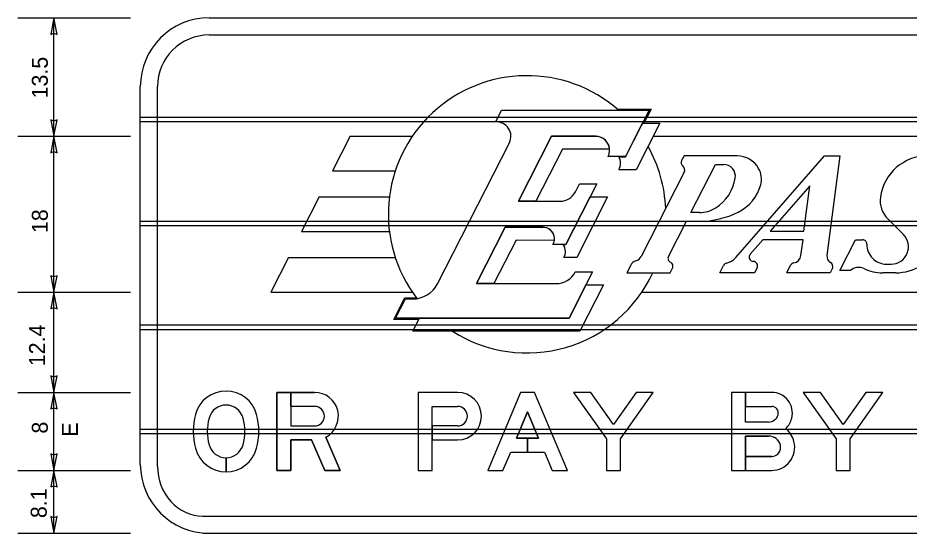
# Model space of a CAD drawing. Extents: x 319706 to 320346, y 1621790 to 1622121.
# Drawn here: x 319878.9 to 319957, y 1621942.3 to 1621987.5 of the extents above; entities that cross this region are included whole.
import ezdxf

# ---------------------------------------------------------------- set-up
doc = ezdxf.new("R2010")
doc.units = 0
for name, color, linetype in [('1', 7, 'Continuous'), ('52', 7, 'Continuous'), ('GSBWFill', 7, 'Continuous'), ('GSColorFill', 7, 'Continuous'), ('GSOutline', 7, 'Continuous'), ('SignPanel', 7, 'Continuous')]:
    doc.layers.add(name, color=color, linetype=linetype)

msp = doc.modelspace()

# ---------------------------------------------------------------- linework, layer by layer
at = {"layer": '1'}
for p, q in [((319878.894, 1621987.477), (319888.758, 1621987.477)), ((319882.055, 1621977.088), (319882.055, 1621987.477)), ((319878.894, 1621977.088), (319888.758, 1621977.088)), ((319882.055, 1621963.418), (319882.055, 1621977.088)), ((319878.894, 1621963.418), (319888.758, 1621963.418)), ((319882.055, 1621954.644), (319882.055, 1621963.418)), ((319878.894, 1621954.644), (319888.758, 1621954.644)), ((319882.055, 1621947.803), (319882.055, 1621954.644)), ((319878.894, 1621947.803), (319888.758, 1621947.803)), ((319882.055, 1621942.302), (319882.055, 1621947.803)), ((319878.894, 1621942.302), (319888.758, 1621942.302))]:
    msp.add_line(p, q, dxfattribs=at)
at = {"layer": '52'}
for p, q in [((319882.055, 1621987.477), (319881.775, 1621986.027)), ((319882.325, 1621986.027), (319882.055, 1621987.477)), ((319881.775, 1621986.027), (319882.055, 1621986.137)), ((319882.055, 1621986.137), (319882.325, 1621986.027)), ((319882.055, 1621978.428), (319881.785, 1621978.538)), ((319881.785, 1621978.538), (319882.055, 1621977.088)), ((319882.055, 1621977.088), (319882.335, 1621978.538)), ((319882.335, 1621978.538), (319882.055, 1621978.428)), ((319882.055, 1621977.088), (319881.775, 1621975.638)), ((319882.325, 1621975.638), (319882.055, 1621977.088)), ((319881.775, 1621975.638), (319882.055, 1621975.748)), ((319882.055, 1621975.748), (319882.325, 1621975.638)), ((319882.055, 1621964.758), (319881.785, 1621964.868)), ((319881.785, 1621964.868), (319882.055, 1621963.418)), ((319882.055, 1621963.418), (319882.335, 1621964.868)), ((319882.335, 1621964.868), (319882.055, 1621964.758)), ((319882.055, 1621963.418), (319881.775, 1621961.968)), ((319882.325, 1621961.968), (319882.055, 1621963.418)), ((319881.775, 1621961.968), (319882.055, 1621962.078)), ((319882.055, 1621962.078), (319882.325, 1621961.968)), ((319882.055, 1621955.984), (319881.785, 1621956.094)), ((319881.785, 1621956.094), (319882.055, 1621954.644)), ((319882.055, 1621954.644), (319882.335, 1621956.094)), ((319882.335, 1621956.094), (319882.055, 1621955.984)), ((319882.055, 1621954.644), (319881.775, 1621953.194)), ((319882.325, 1621953.194), (319882.055, 1621954.644)), ((319881.775, 1621953.194), (319882.055, 1621953.304)), ((319882.055, 1621953.304), (319882.325, 1621953.194)), ((319882.055, 1621949.143), (319881.785, 1621949.253)), ((319881.785, 1621949.253), (319882.055, 1621947.803)), ((319882.055, 1621947.803), (319882.335, 1621949.253)), ((319882.335, 1621949.253), (319882.055, 1621949.143)), ((319882.055, 1621947.803), (319881.775, 1621946.353)), ((319882.325, 1621946.353), (319882.055, 1621947.803)), ((319881.775, 1621946.353), (319882.055, 1621946.463)), ((319882.055, 1621946.463), (319882.325, 1621946.353)), ((319882.055, 1621943.642), (319881.785, 1621943.752)), ((319881.785, 1621943.752), (319882.055, 1621942.302)), ((319882.055, 1621942.302), (319882.335, 1621943.752)), ((319882.335, 1621943.752), (319882.055, 1621943.642))]:
    msp.add_line(p, q, dxfattribs=at)
at = {"layer": 'GSBWFill'}
for p, q in [((319915.192, 1621953.413), (319917.416, 1621953.413)), ((319897.13, 1621948.915), (319897.13, 1621947.683)), ((319897.131, 1621947.683), (319897.131, 1621948.915))]:
    msp.add_line(p, q, dxfattribs=at)
for points in [[(319905.859, 1621950.713), (319907.119, 1621947.803), (319905.777, 1621947.803), (319904.622, 1621950.471), (319902.809, 1621950.471), (319902.809, 1621947.803), (319901.577, 1621947.803), (319901.577, 1621954.644), (319902.809, 1621954.644), (319902.809, 1621951.703), (319904.885, 1621951.703)], [(319902.809, 1621953.413), (319902.809, 1621954.644), (319904.885, 1621954.644)], [(319917.416, 1621954.644), (319913.961, 1621954.644), (319913.961, 1621947.803), (319915.192, 1621947.803), (319915.192, 1621953.413)], [(319944.654, 1621952.045), (319942.627, 1621952.045), (319942.627, 1621954.644), (319941.395, 1621954.644), (319941.395, 1621947.803), (319942.627, 1621947.803)], [(319944.919, 1621954.644), (319942.627, 1621954.644), (319942.627, 1621953.413), (319944.919, 1621953.413)], [(319904.885, 1621953.413), (319902.809, 1621953.413)], [(319917.416, 1621951.703), (319915.193, 1621951.703), (319915.193, 1621950.471), (319917.416, 1621950.471)], [(319942.627, 1621947.803), (319942.627, 1621950.813), (319944.654, 1621950.813)], [(319944.919, 1621949.034), (319942.627, 1621949.034), (319942.627, 1621947.803), (319944.919, 1621947.803)]]:
    msp.add_lwpolyline(points, dxfattribs=at)
for points in [[(319924.5, 1621950.642), (319923.539, 1621950.642), (319923.539, 1621949.411), (319925.017, 1621949.411), (319925.692, 1621947.803), (319927.028, 1621947.803), (319924.155, 1621954.644), (319922.923, 1621954.644), (319920.05, 1621947.803), (319921.385, 1621947.803), (319922.061, 1621949.411), (319923.539, 1621949.411), (319923.539, 1621950.642), (319922.578, 1621950.642), (319923.539, 1621952.93)], [(319931.68, 1621950.574), (319934.554, 1621954.644), (319933.046, 1621954.644), (319931.065, 1621951.837), (319929.083, 1621954.644), (319927.575, 1621954.644), (319930.449, 1621950.574), (319930.449, 1621947.803), (319931.68, 1621947.803)], [(319951.795, 1621950.574), (319954.668, 1621954.644), (319953.161, 1621954.644), (319951.179, 1621951.837), (319949.197, 1621954.644), (319947.69, 1621954.644), (319950.563, 1621950.574), (319950.563, 1621947.803), (319951.795, 1621947.803)]]:
    msp.add_lwpolyline(points, close=True, dxfattribs=at)
for centre, radius, start, end in [((319897.13, 1621951.991), 2.773, 14.96177, 165.03823), ((319904.885, 1621952.558), 2.087, 297.837, 90), ((319944.919, 1621952.831), 1.813, 345.52249, 90), ((319897.13, 1621951.991), 1.541, 14.96177, 165.03823), ((319904.885, 1621952.558), 0.855, 270, 90), ((319944.919, 1621952.831), 0.582, 345.52249, 90), ((319900.004, 1621951.224), 5.747, 165.03823, 194.96177), ((319900.004, 1621951.224), 4.515, 165.03823, 194.96177), ((319894.257, 1621951.224), 4.515, 345.03823, 14.96177), ((319894.257, 1621951.224), 5.747, 345.03823, 14.96177), ((319944.654, 1621952.9), 0.855, 270, 345.52249), ((319944.654, 1621952.9), 2.087, 316.7114, 345.52249), ((319944.654, 1621949.753), 2.292, 14.47751, 48.4921), ((319944.654, 1621949.753), 1.06, 14.47751, 90), ((319897.13, 1621950.456), 2.773, 194.96177, 270), ((319897.13, 1621950.456), 1.541, 194.96177, 270), ((319897.13, 1621950.456), 1.541, 270.01272, 345.03823), ((319897.13, 1621950.456), 2.773, 270.00707, 345.03823), ((319944.919, 1621949.821), 2.018, 270, 14.47751), ((319944.919, 1621949.821), 0.787, 270, 14.47751)]:
    msp.add_arc(centre, radius, start, end, dxfattribs=at)
for major_axis in [(0, 2.087), (0, 0.855)]:
    msp.add_ellipse((319917.416, 1621952.558), major_axis=major_axis, ratio=0.999994, start_param=3.141593, end_param=6.283185, dxfattribs=at)
at = {"layer": 'GSColorFill'}
for p, q in [((319915.192, 1621953.413), (319917.416, 1621953.413)), ((319897.13, 1621948.915), (319897.13, 1621947.683)), ((319897.131, 1621947.683), (319897.131, 1621948.915))]:
    msp.add_line(p, q, dxfattribs=at)
for points in [[(319905.859, 1621950.713), (319907.119, 1621947.803), (319905.777, 1621947.803), (319904.622, 1621950.471), (319902.809, 1621950.471), (319902.809, 1621947.803), (319901.577, 1621947.803), (319901.577, 1621954.644), (319902.809, 1621954.644), (319902.809, 1621951.703), (319904.885, 1621951.703)], [(319902.809, 1621953.413), (319902.809, 1621954.644), (319904.885, 1621954.644)], [(319917.416, 1621954.644), (319913.961, 1621954.644), (319913.961, 1621947.803), (319915.192, 1621947.803), (319915.192, 1621953.413)], [(319944.654, 1621952.045), (319942.627, 1621952.045), (319942.627, 1621954.644), (319941.395, 1621954.644), (319941.395, 1621947.803), (319942.627, 1621947.803)], [(319944.919, 1621954.644), (319942.627, 1621954.644), (319942.627, 1621953.413), (319944.919, 1621953.413)], [(319904.885, 1621953.413), (319902.809, 1621953.413)], [(319917.416, 1621951.703), (319915.193, 1621951.703), (319915.193, 1621950.471), (319917.416, 1621950.471)], [(319942.627, 1621947.803), (319942.627, 1621950.813), (319944.654, 1621950.813)], [(319944.919, 1621949.034), (319942.627, 1621949.034), (319942.627, 1621947.803), (319944.919, 1621947.803)]]:
    msp.add_lwpolyline(points, dxfattribs=at)
for points in [[(319924.5, 1621950.642), (319923.539, 1621950.642), (319923.539, 1621949.411), (319925.017, 1621949.411), (319925.692, 1621947.803), (319927.028, 1621947.803), (319924.155, 1621954.644), (319922.923, 1621954.644), (319920.05, 1621947.803), (319921.385, 1621947.803), (319922.061, 1621949.411), (319923.539, 1621949.411), (319923.539, 1621950.642), (319922.578, 1621950.642), (319923.539, 1621952.93)], [(319931.68, 1621950.574), (319934.554, 1621954.644), (319933.046, 1621954.644), (319931.065, 1621951.837), (319929.083, 1621954.644), (319927.575, 1621954.644), (319930.449, 1621950.574), (319930.449, 1621947.803), (319931.68, 1621947.803)], [(319951.795, 1621950.574), (319954.668, 1621954.644), (319953.161, 1621954.644), (319951.179, 1621951.837), (319949.197, 1621954.644), (319947.69, 1621954.644), (319950.563, 1621950.574), (319950.563, 1621947.803), (319951.795, 1621947.803)]]:
    msp.add_lwpolyline(points, close=True, dxfattribs=at)
for centre, radius, start, end in [((319897.13, 1621951.991), 2.773, 14.96177, 165.03823), ((319904.885, 1621952.558), 2.087, 297.837, 90), ((319944.919, 1621952.831), 1.813, 345.52249, 90), ((319897.13, 1621951.991), 1.541, 14.96177, 165.03823), ((319904.885, 1621952.558), 0.855, 270, 90), ((319944.919, 1621952.831), 0.582, 345.52249, 90), ((319900.004, 1621951.224), 5.747, 165.03823, 194.96177), ((319900.004, 1621951.224), 4.515, 165.03823, 194.96177), ((319894.257, 1621951.224), 4.515, 345.03823, 14.96177), ((319894.257, 1621951.224), 5.747, 345.03823, 14.96177), ((319944.654, 1621952.9), 0.855, 270, 345.52249), ((319944.654, 1621952.9), 2.087, 316.7114, 345.52249), ((319944.654, 1621949.753), 2.292, 14.47751, 48.4921), ((319944.654, 1621949.753), 1.06, 14.47751, 90), ((319897.13, 1621950.456), 2.773, 194.96177, 270), ((319897.13, 1621950.456), 1.541, 194.96177, 270), ((319897.13, 1621950.456), 1.541, 270.01272, 345.03823), ((319897.13, 1621950.456), 2.773, 270.00707, 345.03823), ((319944.919, 1621949.821), 2.018, 270, 14.47751), ((319944.919, 1621949.821), 0.787, 270, 14.47751)]:
    msp.add_arc(centre, radius, start, end, dxfattribs=at)
for major_axis in [(0, 2.087), (0, 0.855)]:
    msp.add_ellipse((319917.416, 1621952.558), major_axis=major_axis, ratio=0.999994, start_param=3.141593, end_param=6.283185, dxfattribs=at)
at = {"layer": 'GSOutline'}
for p, q in [((319915.192, 1621953.413), (319917.416, 1621953.413)), ((319915.192, 1621950.471), (319917.416, 1621950.471)), ((319941.395, 1621947.803), (319944.919, 1621947.803))]:
    msp.add_line(p, q, dxfattribs=at)
for points in [[(319904.885, 1621954.644), (319901.577, 1621954.644), (319901.577, 1621947.803), (319902.809, 1621947.803), (319902.809, 1621950.471), (319904.622, 1621950.471), (319905.777, 1621947.803), (319907.119, 1621947.803), (319905.859, 1621950.713)], [(319917.416, 1621954.644), (319913.961, 1621954.644), (319913.961, 1621947.803), (319915.192, 1621947.803), (319915.192, 1621950.471)], [(319944.919, 1621954.644), (319941.395, 1621954.644), (319941.395, 1621947.803)], [(319904.885, 1621953.413), (319902.809, 1621953.413), (319902.809, 1621951.703), (319904.885, 1621951.703)], [(319917.416, 1621951.703), (319915.192, 1621951.703), (319915.192, 1621953.413)], [(319944.654, 1621952.045), (319942.627, 1621952.045), (319942.627, 1621953.413), (319944.919, 1621953.413)], [(319944.654, 1621950.813), (319942.627, 1621950.813), (319942.627, 1621949.034), (319944.919, 1621949.034)]]:
    msp.add_lwpolyline(points, dxfattribs=at)
for points in [[(319922.061, 1621949.411), (319925.017, 1621949.411), (319925.692, 1621947.803), (319927.028, 1621947.803), (319924.155, 1621954.644), (319922.923, 1621954.644), (319920.05, 1621947.803), (319921.385, 1621947.803)], [(319931.68, 1621950.574), (319934.554, 1621954.644), (319933.046, 1621954.644), (319931.065, 1621951.837), (319929.083, 1621954.644), (319927.575, 1621954.644), (319930.449, 1621950.574), (319930.449, 1621947.803), (319931.68, 1621947.803)], [(319951.795, 1621950.574), (319954.668, 1621954.644), (319953.161, 1621954.644), (319951.179, 1621951.837), (319949.197, 1621954.644), (319947.69, 1621954.644), (319950.563, 1621950.574), (319950.563, 1621947.803), (319951.795, 1621947.803)], [(319924.5, 1621950.642), (319923.539, 1621952.93), (319922.578, 1621950.642)]]:
    msp.add_lwpolyline(points, close=True, dxfattribs=at)
for centre, radius, start, end in [((319897.13, 1621951.991), 2.773, 14.96177, 165.03823), ((319904.885, 1621952.558), 2.087, 297.837, 90), ((319944.919, 1621952.831), 1.813, 345.52249, 90), ((319897.13, 1621951.991), 1.541, 14.96177, 165.03823), ((319904.885, 1621952.558), 0.855, 270, 90), ((319944.919, 1621952.831), 0.582, 345.52249, 90), ((319900.004, 1621951.224), 5.747, 165.03823, 194.96177), ((319900.004, 1621951.224), 4.515, 165.03823, 194.96177), ((319894.257, 1621951.224), 4.515, 345.03823, 14.96177), ((319894.257, 1621951.224), 5.747, 345.03823, 14.96177), ((319944.654, 1621952.9), 0.855, 270, 345.52249), ((319944.654, 1621952.9), 2.087, 316.7114, 345.52249), ((319944.654, 1621949.753), 2.292, 14.47751, 48.4921), ((319944.654, 1621949.753), 1.06, 14.47751, 90), ((319897.13, 1621950.456), 2.773, 194.96177, 345.03823), ((319897.13, 1621950.456), 1.541, 194.96177, 345.03823), ((319944.919, 1621949.821), 2.018, 270, 14.47751), ((319944.919, 1621949.821), 0.787, 270, 14.47751)]:
    msp.add_arc(centre, radius, start, end, dxfattribs=at)
for major_axis in [(0, 2.087), (0, 0.855)]:
    msp.add_ellipse((319917.416, 1621952.558), major_axis=major_axis, ratio=0.999994, start_param=3.141593, end_param=6.283185, dxfattribs=at)
at = {"layer": 'SignPanel'}
for p, q in [((319895.646, 1621987.477), (319992.019, 1621987.477)), ((319895.646, 1621985.972), (319992.019, 1621985.972)), ((319889.623, 1621948.326), (319889.623, 1621981.453)), ((319891.129, 1621948.167), (319891.129, 1621981.453)), ((319931.402, 1621979.48), (319934.362, 1621979.48)), ((319934.362, 1621979.48), (319933.725, 1621978.228)), ((319889.623, 1621978.771), (319998.043, 1621978.771)), ((319920.749, 1621978.347), (319921.266, 1621979.367)), ((319921.266, 1621979.367), (319934.178, 1621979.367)), ((319934.178, 1621979.367), (319932.11, 1621975.306)), ((319889.623, 1621978.394), (319998.043, 1621978.394)), ((319932.106, 1621975.302), (319933.597, 1621978.228)), ((319932.106, 1621975.302), (319933.597, 1621978.228)), ((319935.131, 1621978.228), (319933.062, 1621974.166)), ((319935.131, 1621978.228), (319933.062, 1621974.166)), ((319933.597, 1621978.228), (319935.131, 1621978.228)), ((319933.597, 1621978.228), (319935.131, 1621978.228)), ((319908.004, 1621977.088), (319906.457, 1621974.05)), ((319908.004, 1621977.088), (319913.45, 1621977.088)), ((319925.642, 1621977.088), (319922.74, 1621971.393)), ((319922.74, 1621971.393), (319925.642, 1621977.088)), ((319922.74, 1621971.393), (319925.642, 1621977.088)), ((319929.512, 1621977.088), (319925.642, 1621977.088)), ((319925.642, 1621977.088), (319929.512, 1621977.088)), ((319925.642, 1621977.088), (319929.512, 1621977.088)), ((319934.55, 1621977.088), (319977.874, 1621977.088)), ((319915.645, 1621964.158), (319921.949, 1621976.529)), ((319926.596, 1621975.95), (319924.274, 1621971.393)), ((319926.596, 1621975.95), (319924.274, 1621971.393)), ((319930.727, 1621975.95), (319926.596, 1621975.95)), ((319930.727, 1621975.95), (319926.596, 1621975.95)), ((319932.11, 1621975.306), (319930.59, 1621975.306)), ((319931.542, 1621975.302), (319932.106, 1621975.302)), ((319931.542, 1621975.302), (319932.106, 1621975.302)), ((319937.243, 1621975.379), (319937.035, 1621974.974)), ((319941.893, 1621975.379), (319937.243, 1621975.379)), ((319941.777, 1621966.46), (319949.532, 1621975.379)), ((319949.532, 1621975.379), (319950.899, 1621975.379)), ((319950.899, 1621975.379), (319949.762, 1621966.64)), ((319906.457, 1621974.05), (319911.954, 1621974.05)), ((319933.062, 1621974.166), (319931.544, 1621974.166)), ((319933.062, 1621974.166), (319931.544, 1621974.166)), ((319937.256, 1621973.944), (319933.495, 1621966.564)), ((319937.839, 1621970.405), (319939.987, 1621974.619)), ((319939.987, 1621974.619), (319940.718, 1621974.619)), ((319929.597, 1621972.912), (319926.889, 1621967.595)), ((319927.726, 1621972.222), (319928.078, 1621972.912)), ((319928.078, 1621972.912), (319929.597, 1621972.912)), ((319948.26, 1621972.76), (319944.793, 1621968.771)), ((319947.742, 1621968.771), (319948.26, 1621972.76)), ((319905.298, 1621971.772), (319903.751, 1621968.735)), ((319905.298, 1621971.772), (319911.439, 1621971.772)), ((319926.889, 1621967.595), (319929.017, 1621971.772)), ((319926.889, 1621967.595), (319929.017, 1621971.772)), ((319930.551, 1621971.772), (319927.842, 1621966.456)), ((319930.551, 1621971.772), (319927.842, 1621966.456)), ((319929.017, 1621971.772), (319930.551, 1621971.772)), ((319929.017, 1621971.772), (319930.551, 1621971.772)), ((319922.74, 1621971.393), (319926.374, 1621971.393)), ((319924.274, 1621971.393), (319922.74, 1621971.393)), ((319924.274, 1621971.393), (319922.74, 1621971.393)), ((319938.59, 1621970.405), (319937.839, 1621970.405)), ((319889.623, 1621969.661), (319998.043, 1621969.661)), ((319889.623, 1621969.286), (319998.043, 1621969.286)), ((319935.88, 1621966.564), (319937.451, 1621969.645)), ((319937.451, 1621969.645), (319938.59, 1621969.645)), ((319956.454, 1621968.479), (319955.089, 1621969.846)), ((319903.751, 1621968.735), (319911.439, 1621968.735)), ((319921.58, 1621969.114), (319919.064, 1621964.178)), ((319919.064, 1621964.178), (319921.58, 1621969.114)), ((319919.064, 1621964.178), (319921.58, 1621969.114)), ((319924.913, 1621969.114), (319921.58, 1621969.114)), ((319921.58, 1621969.114), (319924.769, 1621969.104)), ((319921.58, 1621969.114), (319924.769, 1621969.104)), ((319944.793, 1621968.771), (319947.742, 1621968.771)), ((319922.533, 1621967.972), (319920.598, 1621964.178)), ((319922.533, 1621967.972), (319920.598, 1621964.178)), ((319925.885, 1621967.961), (319922.533, 1621967.972)), ((319925.885, 1621967.961), (319922.533, 1621967.972)), ((319944.135, 1621968.011), (319943.034, 1621966.748)), ((319947.664, 1621968.011), (319944.135, 1621968.011)), ((319947.484, 1621966.64), (319947.664, 1621968.011)), ((319950.894, 1621965.317), (319952.272, 1621968.024)), ((319952.272, 1621968.024), (319952.882, 1621968.024)), ((319926.889, 1621967.595), (319925.745, 1621967.595)), ((319926.65, 1621967.595), (319926.889, 1621967.595)), ((319926.65, 1621967.595), (319926.889, 1621967.595)), ((319902.592, 1621966.456), (319901.046, 1621963.418)), ((319902.592, 1621966.456), (319911.954, 1621966.456)), ((319927.842, 1621966.456), (319926.703, 1621966.456)), ((319927.842, 1621966.456), (319926.703, 1621966.456)), ((319932.572, 1621965.796), (319932.23, 1621965.126)), ((319936.028, 1621965.126), (319936.234, 1621965.533)), ((319940.379, 1621965.126), (319940.71, 1621965.777)), ((319943.642, 1621965.565), (319943.417, 1621965.126)), ((319946.241, 1621965.126), (319946.576, 1621965.786)), ((319950.238, 1621965.518), (319950.037, 1621965.126)), ((319954.97, 1621965.886), (319955.381, 1621965.886)), ((319929.238, 1621965.2), (319927.169, 1621961.14)), ((319927.718, 1621965.2), (319929.238, 1621965.2)), ((319932.23, 1621965.126), (319936.028, 1621965.126)), ((319943.417, 1621965.126), (319940.379, 1621965.126)), ((319950.037, 1621965.126), (319946.241, 1621965.126)), ((319951.816, 1621965.317), (319950.894, 1621965.317)), ((319955.789, 1621965.126), (319954.647, 1621965.126)), ((319919.064, 1621964.178), (319926.035, 1621964.178)), ((319920.598, 1621964.178), (319919.064, 1621964.178)), ((319920.598, 1621964.178), (319919.064, 1621964.178)), ((319927.169, 1621961.14), (319928.657, 1621964.061)), ((319927.169, 1621961.14), (319928.657, 1621964.061)), ((319930.192, 1621964.061), (319928.122, 1621960)), ((319930.192, 1621964.061), (319928.122, 1621960)), ((319928.657, 1621964.061), (319930.192, 1621964.061)), ((319928.657, 1621964.061), (319930.192, 1621964.061)), ((319901.046, 1621963.418), (319913.45, 1621963.418)), ((319933.543, 1621963.418), (319970.908, 1621963.418)), ((319911.818, 1621961.04), (319912.781, 1621962.93)), ((319911.981, 1621961.14), (319912.843, 1621962.831)), ((319912.781, 1621962.93), (319913.479, 1621962.93)), ((319912.843, 1621962.831), (319913.479, 1621962.831)), ((319914.028, 1621961.04), (319911.818, 1621961.04)), ((319927.169, 1621961.14), (319911.981, 1621961.14)), ((319913.5, 1621960), (319914.079, 1621961.14)), ((319913.5, 1621960), (319914.079, 1621961.14)), ((319914.079, 1621961.14), (319927.169, 1621961.14)), ((319914.079, 1621961.14), (319927.169, 1621961.14)), ((319889.623, 1621960.551), (319998.043, 1621960.551)), ((319889.623, 1621960.146), (319998.043, 1621960.146)), ((319928.122, 1621960), (319913.5, 1621960)), ((319928.122, 1621960), (319913.5, 1621960)), ((319889.623, 1621951.412), (319998.043, 1621951.412)), ((319889.623, 1621951.036), (319998.043, 1621951.036)), ((319895.082, 1621943.808), (319992.019, 1621943.808)), ((319895.113, 1621942.302), (319992.019, 1621942.302))]:
    msp.add_line(p, q, dxfattribs=at)
for centre, radius, start, end in [((319895.646, 1621981.454), 6.023, 90, 180), ((319895.646, 1621981.454), 4.517, 90, 180), ((319923.496, 1621970.252), 12.151, 48.59038, 217.4727), ((319920.831, 1621977.097), 1.253, 332.99985, 93.80449), ((319929.513, 1621975.872), 1.215, 332.20885, 90), ((319929.513, 1621975.872), 1.215, 3.58332, 90), ((319929.513, 1621975.872), 1.215, 3.58332, 90), ((319923.496, 1621970.252), 12.151, 2.42356, 29.27706), ((319930.467, 1621974.733), 1.215, 332.20885, 27.91266), ((319930.467, 1621974.733), 1.215, 332.20885, 27.91266), ((319937.373, 1621974.8), 0.38, 152.97842, 231.16017), ((319941.893, 1621973.214), 2.164, 29.43149, 90), ((319958.58, 1621971.201), 4.177, 90, 172.30892), ((319936.849, 1621974.15), 0.456, 333.00266, 51.16017), ((319940.718, 1621973.594), 1.025, 351.07601, 90), ((319942.124, 1621973.344), 1.899, 344.70738, 29.43149), ((319937.979, 1621974.024), 3.797, 302.42062, 351.07601), ((319940.293, 1621973.845), 3.797, 296.64315, 344.70738), ((319926.373, 1621972.91), 1.519, 270, 332.98829), ((319956.698, 1621971.455), 2.278, 172.30892, 225), ((319938.59, 1621973.062), 2.658, 270, 302.42062), ((319938.59, 1621977.239), 7.595, 270, 296.64315), ((319924.912, 1621968.125), 0.987, 350.35016, 98.33436), ((319924.912, 1621968.125), 0.987, 350.35016, 98.33436), ((319924.912, 1621968.125), 0.987, 327.42103, 90), ((319955.38, 1621967.404), 1.519, 270, 45), ((319952.882, 1621967.642), 0.38, 358.66645, 90), ((319925.871, 1621966.986), 0.987, 327.42103, 37.97987), ((319925.871, 1621966.986), 0.987, 327.42103, 37.97987), ((319954.97, 1621967.594), 1.709, 178.66645, 270), ((319955.788, 1621969.303), 4.177, 270, 334.94996), ((319933.248, 1621965.45), 0.759, 106.43168, 152.97425), ((319932.818, 1621966.907), 0.759, 286.43167, 332.99588), ((319936.218, 1621966.391), 0.38, 152.98839, 244.78323), ((319940.63, 1621967.455), 1.519, 282.71621, 318.99659), ((319943.32, 1621966.496), 0.38, 138.98241, 268.68694), ((319946.731, 1621966.737), 0.759, 279.2397, 352.56317), ((319950.364, 1621966.56), 0.608, 172.58839, 241.86732), ((319935.895, 1621965.704), 0.38, 333.02391, 64.78322), ((319941.048, 1621965.603), 0.38, 102.71621, 153.02391), ((319943.303, 1621965.737), 0.38, 332.97842, 88.68694), ((319946.914, 1621965.612), 0.38, 99.2397, 153.02391), ((319949.898, 1621965.689), 0.38, 332.97842, 61.86732), ((319952.543, 1621964.54), 1.063, 64.37946, 133.18921), ((319954.645, 1621968.923), 3.797, 244.37946, 270), ((319923.496, 1621970.252), 12.151, 237.53826, 335.04698), ((319926.033, 1621966.075), 1.899, 270, 332.5096), ((319913.479, 1621965.261), 2.43, 270, 332.99913), ((319913.479, 1621965.261), 2.332, 270, 277.50379), ((319895.646, 1621948.325), 6.023, 180, 270)]:
    msp.add_arc(centre, radius, start, end, dxfattribs=at)
msp.add_ellipse((319895.081, 1621948.167), major_axis=(0, 4.36), ratio=0.906668, start_param=1.570796, end_param=3.141593, dxfattribs=at)

# ---------------------------------------------------------------- texts
at = {"layer": '1'}
for s, p in [('13.5', (319881.521, 1621980.412)), ('18', (319881.521, 1621968.611)), ('12.4', (319881.277, 1621956.939)), ('8', (319881.521, 1621951.032)), ('E', (319884.154, 1621950.764)), ('8.1', (319881.424, 1621943.625))]:
    msp.add_text(s, height=1.4, rotation=90, dxfattribs=at).set_placement(p)

doc.saveas('drawing.dxf')
